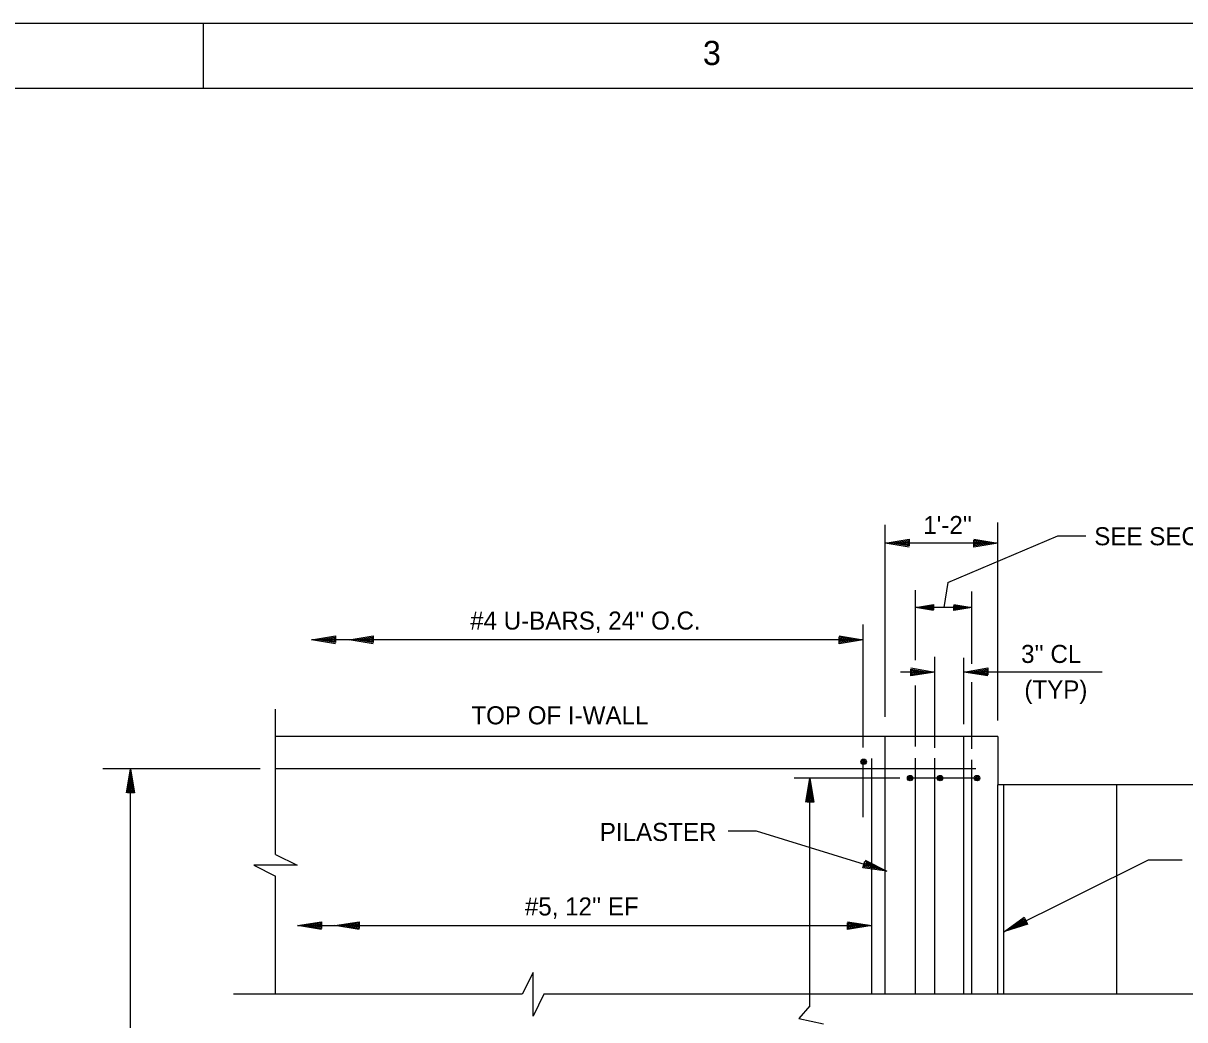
# Model space of a CAD drawing. Extents: x 22369.6 to 22428.3, y 22369.6 to 22415.
# Drawn here: x 22390.66 to 22402.68, y 22404.66 to 22414.97 of the extents above; entities that cross this region are included whole.
import ezdxf

# ---------------------------------------------------------------- set-up
doc = ezdxf.new("R2010")
doc.units = 0
for name, color, linetype in [('Level 1', 7, 'Continuous'), ('Level 10', 7, 'Continuous'), ('Level 2', 7, 'Continuous'), ('Level 4', 7, 'Continuous'), ('Level 7', 7, 'Continuous'), ('Level 9', 7, 'Continuous')]:
    doc.layers.add(name, color=color, linetype=linetype)

msp = doc.modelspace()

# ---------------------------------------------------------------- linework, layer by layer
at = {"layer": 'Level 1'}
for p, q in [((22399.582, 22407.79), (22399.582, 22409.776)), ((22400.749, 22407.752), (22400.749, 22409.801)), ((22400.749, 22409.589), (22399.582, 22409.589)), ((22399.582, 22409.589), (22399.582, 22409.589)), ((22399.651, 22409.589), (22399.651, 22409.589)), ((22400.231, 22409.18), (22401.368, 22409.662)), ((22400.679, 22409.589), (22400.679, 22409.589)), ((22400.749, 22409.589), (22400.749, 22409.589)), ((22401.368, 22409.662), (22401.659, 22409.662)), ((22399.894, 22408.376), (22399.894, 22409.102)), ((22400.231, 22409.18), (22400.187, 22408.924)), ((22400.478, 22408.341), (22400.478, 22409.089)), ((22400.478, 22408.922), (22399.894, 22408.922)), ((22399.894, 22408.922), (22399.894, 22408.922)), ((22399.946, 22408.922), (22399.946, 22408.922)), ((22400.426, 22408.922), (22400.426, 22408.922)), ((22400.478, 22408.922), (22400.478, 22408.922)), ((22399.355, 22407.474), (22399.355, 22408.747)), ((22394.274, 22408.617), (22394.274, 22408.617)), ((22394.285, 22408.63), (22394.285, 22408.63)), ((22393.646, 22408.589), (22393.646, 22408.589)), ((22399.355, 22408.589), (22393.646, 22408.589)), ((22393.715, 22408.589), (22393.715, 22408.589)), ((22394.241, 22408.589), (22394.241, 22408.589)), ((22394.263, 22408.603), (22394.263, 22408.603)), ((22394.263, 22408.585), (22394.263, 22408.585)), ((22394.274, 22408.571), (22394.274, 22408.571)), ((22394.285, 22408.559), (22394.285, 22408.559)), ((22394.285, 22408.547), (22394.285, 22408.547)), ((22399.285, 22408.589), (22399.285, 22408.589)), ((22399.355, 22408.589), (22399.355, 22408.589)), ((22400.096, 22407.471), (22400.096, 22408.411)), ((22400.394, 22407.717), (22400.394, 22408.402)), ((22400.096, 22408.255), (22399.739, 22408.255)), ((22400.026, 22408.255), (22400.026, 22408.255)), ((22400.096, 22408.255), (22400.096, 22408.255)), ((22401.826, 22408.255), (22400.394, 22408.255)), ((22400.394, 22408.255), (22400.394, 22408.255)), ((22400.464, 22408.255), (22400.464, 22408.255)), ((22400.478, 22407.462), (22400.478, 22408.151)), ((22399.894, 22407.486), (22399.894, 22408.116)), ((22393.273, 22406.369), (22393.273, 22407.872)), ((22393.114, 22407.255), (22391.489, 22407.255)), ((22391.773, 22400.88), (22391.773, 22407.255)), ((22391.773, 22407.255), (22391.773, 22407.255)), ((22391.773, 22407.186), (22391.773, 22407.186)), ((22399.734, 22407.158), (22398.639, 22407.158)), ((22398.803, 22404.803), (22398.803, 22407.158)), ((22398.803, 22407.158), (22398.803, 22407.158)), ((22398.803, 22407.089), (22398.803, 22407.089)), ((22397.959, 22406.613), (22398.248, 22406.613)), ((22398.248, 22406.613), (22399.6, 22406.197)), ((22399.534, 22406.217), (22399.534, 22406.217)), ((22400.815, 22405.572), (22402.306, 22406.312)), ((22402.306, 22406.312), (22402.654, 22406.312)), ((22393.273, 22404.922), (22393.273, 22406.145)), ((22399.6, 22406.197), (22399.6, 22406.197)), ((22393.5, 22405.632), (22393.5, 22405.632)), ((22393.5, 22405.632), (22399.442, 22405.632)), ((22393.569, 22405.632), (22393.569, 22405.632)), ((22394.095, 22405.632), (22394.095, 22405.632)), ((22394.117, 22405.647), (22394.117, 22405.647)), ((22394.117, 22405.628), (22394.117, 22405.628)), ((22394.128, 22405.66), (22394.128, 22405.66)), ((22394.128, 22405.615), (22394.128, 22405.615)), ((22394.139, 22405.673), (22394.139, 22405.673)), ((22399.373, 22405.632), (22399.373, 22405.632)), ((22399.442, 22405.632), (22399.442, 22405.632)), ((22400.877, 22405.603), (22400.877, 22405.603)), ((22394.139, 22405.603), (22394.139, 22405.603)), ((22394.139, 22405.591), (22394.139, 22405.591)), ((22400.815, 22405.572), (22400.815, 22405.572)), ((22395.827, 22404.922), (22392.839, 22404.922)), ((22404.34, 22404.922), (22396.051, 22404.922)), ((22398.803, 22404.803), (22398.687, 22404.67)), ((22398.687, 22404.67), (22398.942, 22404.618))]:
    msp.add_line(p, q, dxfattribs=at)
msp.add_lwpolyline([(22369.621, 22414.965), (22428.288, 22414.965), (22428.288, 22369.621), (22369.621, 22369.621)], close=True, dxfattribs=at)
for points in [[(22399.831, 22409.547), (22399.582, 22409.589), (22399.831, 22409.63), (22399.831, 22409.559), (22399.651, 22409.589), (22399.821, 22409.617), (22399.821, 22409.571), (22399.718, 22409.589), (22399.81, 22409.603), (22399.81, 22409.585), (22399.787, 22409.589)], [(22400.499, 22409.63), (22400.749, 22409.589), (22400.499, 22409.547), (22400.499, 22409.618), (22400.679, 22409.589), (22400.51, 22409.561), (22400.51, 22409.606), (22400.613, 22409.589), (22400.521, 22409.574), (22400.521, 22409.593), (22400.543, 22409.589)], [(22400.081, 22408.891), (22399.894, 22408.922), (22400.081, 22408.953), (22400.081, 22408.9), (22399.946, 22408.922), (22400.073, 22408.943), (22400.073, 22408.909), (22399.996, 22408.922), (22400.065, 22408.933), (22400.065, 22408.919), (22400.048, 22408.922)], [(22400.291, 22408.953), (22400.478, 22408.922), (22400.291, 22408.891), (22400.291, 22408.944), (22400.426, 22408.922), (22400.299, 22408.901), (22400.299, 22408.935), (22400.376, 22408.922), (22400.307, 22408.911), (22400.307, 22408.925), (22400.324, 22408.922)], [(22393.895, 22408.547), (22393.646, 22408.589), (22393.895, 22408.63), (22393.895, 22408.559), (22393.715, 22408.589), (22393.885, 22408.617), (22393.885, 22408.571), (22393.782, 22408.589), (22393.874, 22408.603), (22393.874, 22408.585), (22393.851, 22408.589)], [(22394.285, 22408.547), (22394.035, 22408.589), (22394.285, 22408.63), (22394.285, 22408.559), (22394.105, 22408.589), (22394.274, 22408.617), (22394.274, 22408.571), (22394.171, 22408.589), (22394.263, 22408.603), (22394.263, 22408.585), (22394.241, 22408.589)], [(22399.105, 22408.63), (22399.355, 22408.589), (22399.105, 22408.547), (22399.105, 22408.618), (22399.285, 22408.589), (22399.116, 22408.561), (22399.116, 22408.606), (22399.219, 22408.589), (22399.127, 22408.574), (22399.127, 22408.593), (22399.149, 22408.589)], [(22399.846, 22408.297), (22400.096, 22408.255), (22399.846, 22408.214), (22399.846, 22408.285), (22400.026, 22408.255), (22399.857, 22408.227), (22399.857, 22408.273), (22399.96, 22408.255), (22399.868, 22408.241), (22399.868, 22408.259), (22399.89, 22408.255)], [(22400.644, 22408.214), (22400.394, 22408.255), (22400.644, 22408.297), (22400.644, 22408.226), (22400.464, 22408.255), (22400.633, 22408.283), (22400.633, 22408.238), (22400.53, 22408.255), (22400.622, 22408.27), (22400.622, 22408.251), (22400.6, 22408.255)], [(22391.732, 22407.006), (22391.773, 22407.255), (22391.814, 22407.006), (22391.744, 22407.006), (22391.773, 22407.186), (22391.801, 22407.017), (22391.756, 22407.017), (22391.773, 22407.119), (22391.788, 22407.027), (22391.769, 22407.027), (22391.773, 22407.05)], [(22398.761, 22406.909), (22398.803, 22407.158), (22398.844, 22406.909), (22398.773, 22406.909), (22398.803, 22407.089), (22398.831, 22406.92), (22398.785, 22406.92), (22398.803, 22407.022), (22398.817, 22406.93), (22398.799, 22406.93), (22398.803, 22406.953)], [(22393.273, 22406.369), (22393.498, 22406.257), (22393.049, 22406.257), (22393.273, 22406.145)], [(22399.374, 22406.309), (22399.6, 22406.197), (22399.35, 22406.23), (22399.371, 22406.298), (22399.534, 22406.217), (22399.364, 22406.24), (22399.377, 22406.283), (22399.47, 22406.237), (22399.378, 22406.25), (22399.384, 22406.267), (22399.404, 22406.257)], [(22393.749, 22405.591), (22393.5, 22405.632), (22393.749, 22405.673), (22393.749, 22405.603), (22393.569, 22405.632), (22393.739, 22405.66), (22393.739, 22405.615), (22393.636, 22405.632), (22393.728, 22405.647), (22393.728, 22405.628), (22393.705, 22405.632)], [(22394.139, 22405.591), (22393.889, 22405.632), (22394.139, 22405.673), (22394.139, 22405.603), (22393.959, 22405.632), (22394.128, 22405.66), (22394.128, 22405.615), (22394.025, 22405.632), (22394.117, 22405.647), (22394.117, 22405.628), (22394.095, 22405.632)], [(22399.193, 22405.673), (22399.442, 22405.632), (22399.193, 22405.591), (22399.193, 22405.661), (22399.373, 22405.632), (22399.203, 22405.604), (22399.203, 22405.649), (22399.306, 22405.632), (22399.214, 22405.617), (22399.214, 22405.636), (22399.237, 22405.632)], [(22401.056, 22405.646), (22400.815, 22405.572), (22401.02, 22405.72), (22401.051, 22405.657), (22400.877, 22405.603), (22401.016, 22405.703), (22401.036, 22405.663), (22400.936, 22405.633), (22401.012, 22405.687), (22401.021, 22405.67), (22400.998, 22405.663)], [(22396.051, 22404.922), (22395.939, 22404.697), (22395.939, 22405.147), (22395.827, 22404.922)]]:
    msp.add_lwpolyline(points, dxfattribs=at)
at = {"layer": 'Level 10'}
for p, q in [((22392.528, 22414.293), (22392.528, 22414.965)), ((22400.749, 22407.589), (22393.273, 22407.589)), ((22399.582, 22404.922), (22399.582, 22407.589)), ((22400.749, 22407.589), (22400.749, 22407.089)), ((22399.355, 22406.755), (22399.355, 22407.324)), ((22399.442, 22404.922), (22399.442, 22407.359)), ((22399.894, 22404.922), (22399.894, 22407.365)), ((22400.096, 22404.922), (22400.096, 22407.363)), ((22400.478, 22404.922), (22400.478, 22407.348)), ((22400.521, 22407.255), (22393.273, 22407.255)), ((22400.528, 22407.158), (22399.847, 22407.158)), ((22407.215, 22407.089), (22400.749, 22407.089))]:
    msp.add_line(p, q, dxfattribs=at)
at = {"layer": 'Level 2'}
msp.add_line((22401.978, 22404.922), (22401.978, 22407.089), dxfattribs=at)
for centre, radius in [((22399.359, 22407.327), 0.0281), ((22399.359, 22407.327), 0.0176), ((22399.359, 22407.327), 0.00703), ((22399.84, 22407.158), 0.0281), ((22399.84, 22407.158), 0.0176), ((22399.84, 22407.158), 0.00703), ((22400.15, 22407.158), 0.0281), ((22400.15, 22407.158), 0.0176), ((22400.15, 22407.158), 0.00703), ((22400.532, 22407.158), 0.0281), ((22400.532, 22407.158), 0.0176), ((22400.532, 22407.158), 0.00703)]:
    msp.add_circle(centre, radius, dxfattribs=at)
at = {"layer": 'Level 7'}
for p, q in [((22400.394, 22404.922), (22400.394, 22407.589)), ((22400.749, 22404.922), (22400.749, 22407.089)), ((22400.811, 22404.922), (22400.811, 22407.089))]:
    msp.add_line(p, q, dxfattribs=at)
at = {"layer": 'Level 9'}
msp.add_line((22371.621, 22414.293), (22423.952, 22414.293), dxfattribs=at)

# ---------------------------------------------------------------- texts
at = {"layer": 'Level 1'}
msp.add_text('3', height=0.25, dxfattribs=at).set_placement((22397.696, 22414.533))
at = {"layer": 'Level 4'}
for s, height, p in [("1'-2''", 0.1867, (22399.976, 22409.682)), ('SEE SECTION  B  FOR PILASTER REINFORCEMENT', 0.18667, (22401.745, 22409.566)), ("#4 U-BARS, 24'' O.C.", 0.18667, (22395.288, 22408.694)), ("3'' CL", 0.1867, (22400.988, 22408.349)), ('(TYP)', 0.1867, (22401.022, 22407.981)), ('TOP OF I-WALL', 0.18667, (22395.301, 22407.714)), ('PILASTER', 0.1867, (22396.629, 22406.508)), ("#5, 12'' EF", 0.18667, (22395.854, 22405.737))]:
    msp.add_text(s, height=height, dxfattribs=at).set_placement(p)

doc.saveas('drawing.dxf')
